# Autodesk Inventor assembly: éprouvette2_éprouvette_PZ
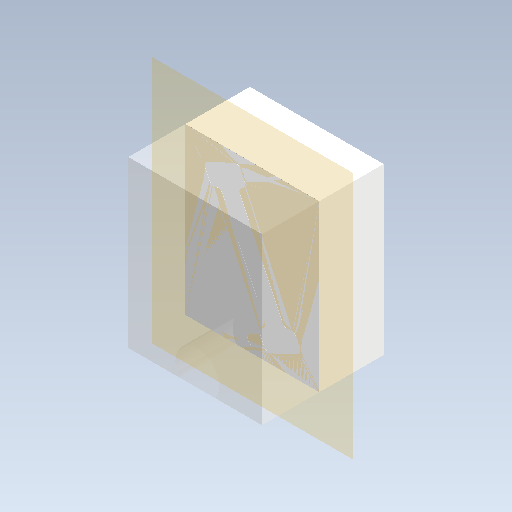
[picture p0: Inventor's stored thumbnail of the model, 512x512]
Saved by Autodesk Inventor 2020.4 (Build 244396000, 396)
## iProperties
Created: 2021-10
Part Number: éprouvette2_éprouvette_PZ
Document SubType Name: Assembly
Designer: mel
Author: mel
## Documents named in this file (7)
- D:\travail\année 2020-2021\itec\prépa injection plastique eduscol\dossier de travail\Ensemble des pièces de l'activité\Conception de moule1\éprouvette2_éprouvette_PZ.iam
- D:\travail\année 2020-2021\itec\prépa injection plastique eduscol\dossier de travail\Ensemble des pièces de l'activité\Conception de moule1\éprouvette2_éprouvette_MP.ipt
- D:\travail\année 2020-2021\itec\prépa injection plastique eduscol\dossier de travail\Ensemble des pièces de l'activité\Conception de moule1\éprouvette2_éprouvette_WP.ipt
- D:\travail\année 2020-2021\itec\prépa injection plastique eduscol\dossier de travail\Ensemble des pièces de l'activité\Conception de moule1\éprouvette2_éprouvette_CR_Base.ipt
- D:\travail\année 2020-2021\itec\prépa injection plastique eduscol\dossier de travail\Ensemble des pièces de l'activité\Conception de moule1\éprouvette2_éprouvette_CR_1.ipt
- D:\travail\année 2020-2021\itec\prépa injection plastique eduscol\dossier de travail\Ensemble des pièces de l'activité\Conception de moule1\éprouvette2_éprouvette_CV_Base.ipt
- D:\travail\année 2020-2021\itec\prépa injection plastique eduscol\dossier de travail\Ensemble des pièces de l'activité\Conception de moule1\éprouvette2_éprouvette_CV_1.ipt
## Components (6 placed, 6 different names)
1. éprouvette2_éprouvette_MP:1 — Affleurement:1, Affleurement:2, Affleurement:3, Affleurement:4, Affleurement:5, Affleurement:6
2. éprouvette2_éprouvette_WP:1 — Affleurement:4, Affleurement:5, Affleurement:6
3. éprouvette2_éprouvette_CR_Base:1 — Affleurement:7, Affleurement:8, Affleurement:9, Affleurement:13, Affleurement:14, Affleurement:15
4. éprouvette2_éprouvette_CR_1:1 — Affleurement:13, Affleurement:14, Affleurement:15
5. éprouvette2_éprouvette_CV_Base:1 — Affleurement:10, Affleurement:11, Affleurement:12, Affleurement:16, Affleurement:17, Affleurement:18
6. éprouvette2_éprouvette_CV_1:1 — Affleurement:16, Affleurement:17, Affleurement:18
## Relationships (18: Flush 18)
- Affleurement:1 [Flush]: éprouvette2_éprouvette_MP:1
- Affleurement:2 [Flush]: éprouvette2_éprouvette_MP:1
- Affleurement:3 [Flush]: éprouvette2_éprouvette_MP:1
- Affleurement:4 [Flush]: éprouvette2_éprouvette_MP:1 ↔ éprouvette2_éprouvette_WP:1
- Affleurement:5 [Flush]: éprouvette2_éprouvette_MP:1 ↔ éprouvette2_éprouvette_WP:1
- Affleurement:6 [Flush]: éprouvette2_éprouvette_MP:1 ↔ éprouvette2_éprouvette_WP:1
- Affleurement:7 [Flush]: éprouvette2_éprouvette_CR_Base:1
- Affleurement:8 [Flush]: éprouvette2_éprouvette_CR_Base:1
- Affleurement:9 [Flush]: éprouvette2_éprouvette_CR_Base:1
- Affleurement:10 [Flush]: éprouvette2_éprouvette_CV_Base:1
- Affleurement:11 [Flush]: éprouvette2_éprouvette_CV_Base:1
- Affleurement:12 [Flush]: éprouvette2_éprouvette_CV_Base:1
- Affleurement:13 [Flush]: éprouvette2_éprouvette_CR_Base:1 ↔ éprouvette2_éprouvette_CR_1:1
- Affleurement:14 [Flush]: éprouvette2_éprouvette_CR_Base:1 ↔ éprouvette2_éprouvette_CR_1:1
- Affleurement:15 [Flush]: éprouvette2_éprouvette_CR_Base:1 ↔ éprouvette2_éprouvette_CR_1:1
- Affleurement:16 [Flush]: éprouvette2_éprouvette_CV_Base:1 ↔ éprouvette2_éprouvette_CV_1:1
- Affleurement:17 [Flush]: éprouvette2_éprouvette_CV_Base:1 ↔ éprouvette2_éprouvette_CV_1:1
- Affleurement:18 [Flush]: éprouvette2_éprouvette_CV_Base:1 ↔ éprouvette2_éprouvette_CV_1:1
